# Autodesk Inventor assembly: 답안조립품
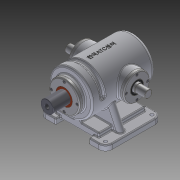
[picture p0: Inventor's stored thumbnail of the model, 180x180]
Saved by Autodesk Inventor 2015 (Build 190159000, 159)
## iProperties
Created: 2015-10
Part Number: 답안조립품
Document SubType Name: Assembly
Designer: youjin05
Mass: 9423.03 g
Surface Area: 4312.61 cm^2
Volume: 2313.44 cm^3
Density: 4.07318 g/cm^3
Author: youjin05
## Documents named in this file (13)
- C:\Users\youjin05\Desktop\351019V1005\답안조립품.iam
- C:\Users\youjin05\Desktop\351019V1005\본체.ipt
- C:\Users\youjin05\Desktop\351019V1005\슬라이드 커버.ipt
- C:\Users\youjin05\Desktop\351019V1005\M4x0.7.ipt
- C:\Users\youjin05\Desktop\351019V1005\축 커버.ipt
- C:\Users\youjin05\Desktop\351019V1005\오일실.ipt
- 오일실.ipt
- C:\Users\youjin05\Desktop\351019V1005\베어링 6205.ipt
- 베어링 6205.ipt
- C:\Users\youjin05\Desktop\351019V1005\편심축.ipt
- C:\Users\youjin05\Desktop\351019V1005\부시.ipt
- C:\Users\youjin05\Desktop\351019V1005\슬라이드.ipt
- C:\Users\youjin05\Desktop\351019V1005\가변스프링.ipt
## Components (13 placed, 2 different names)
1. 가변스프링:1 — Mate:22, Mate:23, Mate:25
2. M4x0.7:1 — Insert:1
3. M4x0.7:4
4. M4x0.7:5
5. M4x0.7:6
6. M4x0.7:3 — Insert:2
7. M4x0.7:7
8. M4x0.7:8
9. M4x0.7:9
10. M4x0.7:2 — Insert:3
11. M4x0.7:10
12. M4x0.7:11
13. M4x0.7:12
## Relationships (6: Insert 3, Mate 3)
- Insert:1: M4x0.7:1
- Insert:2: M4x0.7:3
- Insert:3: M4x0.7:2
- Mate:22: 가변스프링:1
- Mate:23: 가변스프링:1
- Mate:25: 가변스프링:1
